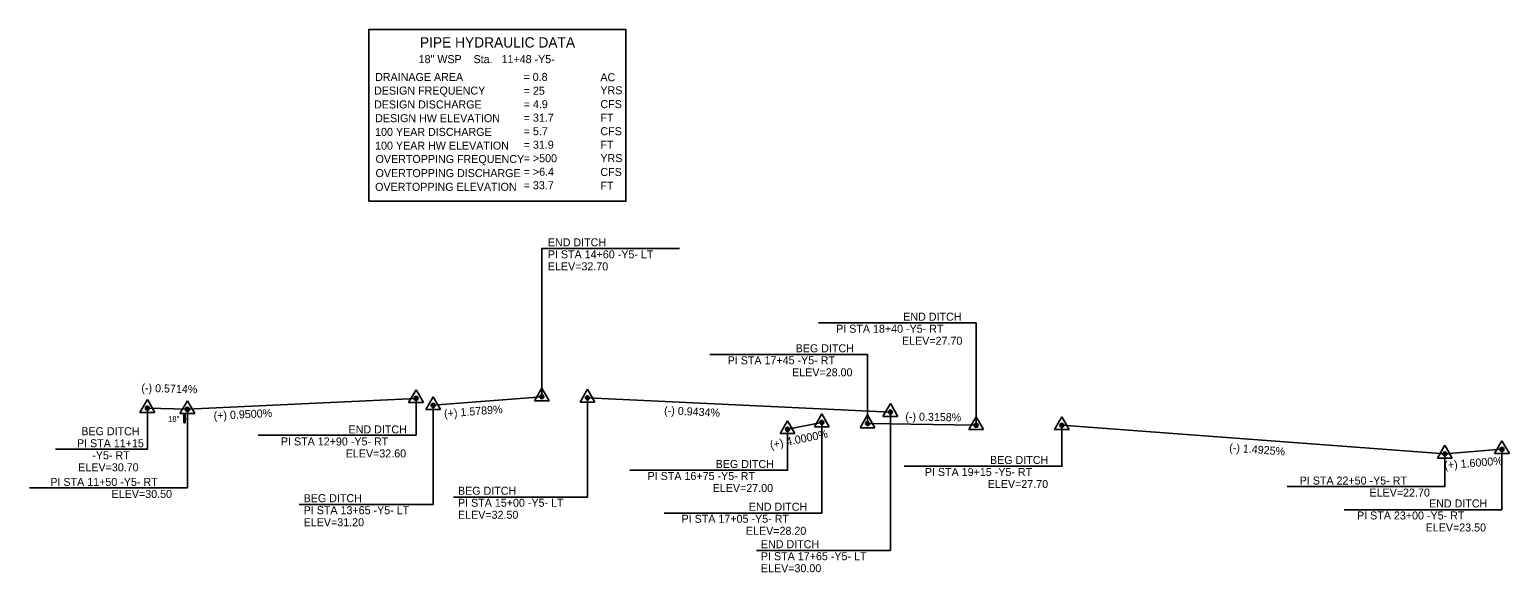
# Model space of a CAD drawing. Extents: x 2179808 to 2190174, y 63168 to 78602.
# Drawn here: x 2186620 to 2187914, y 72167 to 72642 of the extents above; entities that cross this region are included whole.
import ezdxf

# ---------------------------------------------------------------- set-up
doc = ezdxf.new("R2010")
doc.units = 0
for name, color, linetype in [('Default', 7, 'Continuous'), ('Prop Grid Mask', 7, 'Continuous'), ('Prop PFL Cross Pipe CELL', 7, 'Continuous'), ('Prop PFL Cross Pipe Text CELL', 7, 'Continuous'), ('Prop PFL Pipe Hydraulic Data CELL', 7, 'Continuous'), ('Prop Vertical Profile Ditch Grade Left', 7, 'Continuous'), ('Prop Vertical Profile Ditch Grade Left Label', 7, 'Continuous'), ('Prop Vertical Profile Ditch Grade Right', 7, 'Continuous'), ('Prop Vertical Profile Ditch Grade Right Label', 7, 'Continuous'), ('Prop VPI Ditch Grade Left Label', 7, 'Continuous'), ('Prop VPI Ditch Grade Right Label', 7, 'Continuous')]:
    doc.layers.add(name, color=color, linetype=linetype)

msp = doc.modelspace()

# ---------------------------------------------------------------- linework, layer by layer
at = {"layer": 'Default'}
for p, q in [((2186957.7, 72326.8), (2186951.2, 72315.6)), ((2186957.7, 72326.8), (2186964.2, 72315.6)), ((2187067.7, 72328.3), (2187061.2, 72317.1)), ((2187067.7, 72328.3), (2187074.2, 72317.1)), ((2187107.7, 72327.3), (2187101.2, 72316.1)), ((2187107.7, 72327.3), (2187114.2, 72316.1)), ((2186722.7, 72318.3), (2186716.2, 72307.1)), ((2186722.7, 72318.3), (2186729.2, 72307.1)), ((2186757.7, 72317.3), (2186751.2, 72306.1)), ((2186757.7, 72317.3), (2186764.2, 72306.1)), ((2186951.2, 72315.6), (2186964.2, 72315.6)), ((2186972.7, 72320.8), (2186966.2, 72309.6)), ((2186972.7, 72320.8), (2186979.2, 72309.6)), ((2187061.2, 72317.1), (2187074.2, 72317.1)), ((2187101.2, 72316.1), (2187114.2, 72316.1)), ((2187372.7, 72314.8), (2187366.2, 72303.6)), ((2187372.7, 72314.8), (2187379.2, 72303.6)), ((2186716.2, 72307.1), (2186729.2, 72307.1)), ((2186751.2, 72306.1), (2186764.2, 72306.1)), ((2186966.2, 72309.6), (2186979.2, 72309.6)), ((2187282.7, 72299.8), (2187276.2, 72288.6)), ((2187282.7, 72299.8), (2187289.2, 72288.6)), ((2187312.7, 72305.8), (2187306.2, 72294.6)), ((2187312.7, 72305.8), (2187319.2, 72294.6)), ((2187352.7, 72304.8), (2187346.2, 72293.6)), ((2187352.7, 72304.8), (2187359.2, 72293.6)), ((2187366.2, 72303.6), (2187379.2, 72303.6)), ((2187447.7, 72303.3), (2187441.2, 72292.1)), ((2187447.7, 72303.3), (2187454.2, 72292.1)), ((2187522.7, 72303.3), (2187516.2, 72292.1)), ((2187522.7, 72303.3), (2187529.2, 72292.1)), ((2187276.2, 72288.6), (2187289.2, 72288.6)), ((2187306.2, 72294.6), (2187319.2, 72294.6)), ((2187346.2, 72293.6), (2187359.2, 72293.6)), ((2187441.2, 72292.1), (2187454.2, 72292.1)), ((2187516.2, 72292.1), (2187529.2, 72292.1)), ((2187857.7, 72278.3), (2187851.2, 72267.1)), ((2187857.7, 72278.3), (2187864.2, 72267.1)), ((2187907.7, 72282.3), (2187901.2, 72271.1)), ((2187907.7, 72282.3), (2187914.2, 72271.1)), ((2187851.2, 72267.1), (2187864.2, 72267.1)), ((2187901.2, 72271.1), (2187914.2, 72271.1))]:
    msp.add_line(p, q, dxfattribs=at)
for centre, radius in [((2186722.7, 72310.8), 1.75), ((2186957.7, 72319.3), 1.75), ((2186957.7, 72319.3), 1.2), ((2186972.7, 72313.3), 1.75), ((2186972.7, 72313.3), 1.2), ((2187067.7, 72320.8), 1.75), ((2187067.7, 72320.8), 1.2), ((2187107.7, 72319.8), 1.75), ((2187107.7, 72319.8), 1.2), ((2186722.7, 72310.8), 1.2), ((2186757.7, 72309.8), 1.75), ((2186757.7, 72309.8), 1.2), ((2187312.7, 72298.3), 1.75), ((2187312.7, 72298.3), 1.2), ((2187372.7, 72307.3), 1.75), ((2187372.7, 72307.3), 1.2), ((2187282.7, 72292.3), 1.75), ((2187282.7, 72292.3), 1.2), ((2187352.7, 72297.3), 1.75), ((2187352.7, 72297.3), 1.2), ((2187447.7, 72295.8), 1.75), ((2187447.7, 72295.8), 1.2), ((2187522.7, 72295.8), 1.75), ((2187522.7, 72295.8), 1.2), ((2187907.7, 72274.8), 1.75), ((2187907.7, 72274.8), 1.2), ((2187857.7, 72270.8), 1.75), ((2187857.7, 72270.8), 1.2)]:
    msp.add_circle(centre, radius, dxfattribs=at)
at = {"layer": 'Prop Grid Mask'}
msp.add_lwpolyline([(2186916.3, 72491.6), (2187141.3, 72491.6), (2187141.3, 72641.6), (2186916.3, 72641.6)], close=True, dxfattribs=at)
at = {"layer": 'Prop PFL Cross Pipe CELL'}
msp.add_ellipse((2186755.2, 72301.5), major_axis=(0, 3.75), ratio=0.2, dxfattribs=at)
at = {"layer": 'Prop Vertical Profile Ditch Grade Left'}
for p, q in [((2186972.7, 72313.3), (2187067.7, 72320.8)), ((2187107.7, 72319.8), (2187372.7, 72307.3))]:
    msp.add_line(p, q, dxfattribs=at)
at = {"layer": 'Prop Vertical Profile Ditch Grade Right'}
for p, q in [((2187282.7, 72292.3), (2187312.7, 72298.3)), ((2187352.7, 72297.3), (2187447.7, 72295.8))]:
    msp.add_line(p, q, dxfattribs=at)
for points in [[(2186722.7, 72310.8), (2186757.7, 72309.8), (2186957.7, 72319.3)], [(2187522.7, 72295.8), (2187857.7, 72270.8), (2187907.7, 72274.8)]]:
    msp.add_lwpolyline(points, dxfattribs=at)
at = {"layer": 'Prop VPI Ditch Grade Left Label'}
for points in [[(2187067.7, 72320.8), (2187067.7, 72450.2), (2187188.3, 72450.2)], [(2186972.7, 72313.3), (2186972.7, 72226.6), (2186855.5, 72226.6)], [(2187107.7, 72319.8), (2187107.7, 72233.1), (2186990.5, 72233.1)], [(2187372.7, 72307.3), (2187372.7, 72186.4), (2187255.5, 72186.4)]]:
    msp.add_lwpolyline(points, dxfattribs=at)
for centre in [(2186972.7, 72313.3), (2187067.7, 72320.8), (2187107.7, 72319.8), (2187372.7, 72307.3)]:
    msp.add_circle(centre, 0.5, dxfattribs=at)
at = {"layer": 'Prop VPI Ditch Grade Right Label'}
for points in [[(2187447.7, 72295.8), (2187447.7, 72385.2), (2187309.7, 72385.2)], [(2187352.7, 72297.3), (2187352.7, 72357.6), (2187214.7, 72357.6)], [(2186957.7, 72319.3), (2186957.7, 72287.2), (2186819.7, 72287.2)], [(2186757.7, 72309.8), (2186757.7, 72241.2), (2186619.7, 72241.2)], [(2186722.7, 72310.8), (2186722.7, 72275), (2186642.2, 72275)], [(2187282.7, 72292.3), (2187282.7, 72256.5), (2187144.7, 72256.5)], [(2187312.7, 72298.3), (2187312.7, 72219.1), (2187174.7, 72219.1)], [(2187522.7, 72295.8), (2187522.7, 72260), (2187384.7, 72260)], [(2187907.7, 72274.8), (2187907.7, 72222), (2187769.7, 72222)], [(2187857.7, 72270.8), (2187857.7, 72242.4), (2187719.7, 72242.4)]]:
    msp.add_lwpolyline(points, dxfattribs=at)
for centre in [(2186957.7, 72319.3), (2186722.7, 72310.8), (2186757.7, 72309.8), (2187282.7, 72292.3), (2187312.7, 72298.3), (2187352.7, 72297.3), (2187447.7, 72295.8), (2187522.7, 72295.8), (2187907.7, 72274.8), (2187857.7, 72270.8)]:
    msp.add_circle(centre, 0.5, dxfattribs=at)

# ---------------------------------------------------------------- texts
at = {"layer": 'Prop PFL Cross Pipe Text CELL'}
msp.add_text('18"', height=5, dxfattribs=at).set_placement((2186740.8, 72298.8))
at = {"layer": 'Prop PFL Pipe Hydraulic Data CELL'}
for s, height, p in [('PIPE HYDRAULIC DATA', 9, (2186961.1, 72625.9)), ('  18" WSP    Sta.   11+48 -Y5-', 7, (2186954.8, 72612.3)), ('DRAINAGE AREA', 7, (2186921.9, 72596.7)), ('= 0.8    ', 7, (2187051.7, 72596.8)), ('AC', 7, (2187119, 72596.5)), ('DESIGN FREQUENCY', 7, (2186921, 72584.8)), ('= 25 ', 7, (2187051.9, 72584.7)), ('YRS', 7, (2187119, 72585.1)), ('DESIGN DISCHARGE', 7, (2186921, 72572.7)), ('= 4.9     ', 7, (2187051.9, 72572.9)), ('CFS', 7, (2187119, 72573)), ('DESIGN HW ELEVATION', 7, (2186921.9, 72560.7)), ('= 31.7    ', 7, (2187051.9, 72561.1)), ('FT', 7, (2187119, 72561.1)), ('100 YEAR DISCHARGE', 7, (2186921.9, 72548.7)), ('= 5.7     ', 7, (2187051.9, 72549.3)), ('CFS', 7, (2187119, 72549.3)), ('100 YEAR HW ELEVATION', 7, (2186921.9, 72536.7)), ('= 31.9    ', 7, (2187051.9, 72537.5)), ('= >500', 7, (2187051.9, 72525.7)), ('YRS', 7, (2187119, 72525.8)), ('FT', 7, (2187119, 72537.5)), ('OVERTOPPING FREQUENCY', 7, (2186922.3, 72525)), ('OVERTOPPING DISCHARGE', 7, (2186922.3, 72512.7)), ('= >6.4    ', 7, (2187051.9, 72513.9)), ('CFS', 7, (2187119, 72513.7)), ('OVERTOPPING ELEVATION', 7, (2186921.9, 72500.7)), ('= 33.7    ', 7, (2187051.9, 72502.1)), ('FT', 7, (2187119, 72501.7))]:
    msp.add_text(s, height=height, dxfattribs=at).set_placement(p)
at = {"layer": 'Prop Vertical Profile Ditch Grade Left Label'}
for s, rotation, p in [('(+) 1.5789%', 4.4926, (2186982.5, 72302.5)), ('(-) 0.9434%', 357.2994, (2187174.6, 72305.5))]:
    msp.add_text(s, height=7, rotation=rotation, dxfattribs=at).set_placement(p)
at = {"layer": 'Prop Vertical Profile Ditch Grade Right Label'}
for s, rotation, p in [('(-) 0.5714%', 358.3634, (2186717.4, 72325.1)), ('(+) 0.9500%', 2.7195, (2186780.8, 72300.7)), ('(-) 0.3158%', 359.0954, (2187385.7, 72300)), ('(+) 4.0000%', 11.3099, (2187268.1, 72275.1)), ('(-) 1.4925%', 355.7321, (2187668.9, 72273)), ('(+) 1.6000%', 4.5739, (2187857.5, 72257.4))]:
    msp.add_text(s, height=7, rotation=rotation, dxfattribs=at).set_placement(p)
at = {"layer": 'Prop VPI Ditch Grade Left Label'}
for s, p in [('END DITCH', (2187073, 72452.2)), ('PI STA 14+60 -Y5- LT', (2187073, 72441.7)), ('ELEV=32.70', (2187073, 72431.2)), ('BEG DITCH', (2186859.4, 72228.6)), ('BEG DITCH', (2186994.4, 72235.1)), ('PI STA 13+65 -Y5- LT', (2186859.4, 72218.1)), ('PI STA 15+00 -Y5- LT', (2186994.4, 72224.6)), ('ELEV=31.20', (2186859.4, 72207.6)), ('ELEV=32.50', (2186994.4, 72214.1)), ('END DITCH', (2187259.4, 72188.4)), ('PI STA 17+65 -Y5- LT', (2187259.4, 72177.9)), ('ELEV=30.00', (2187259.4, 72167.4))]:
    msp.add_text(s, height=7, dxfattribs=at).set_placement(p)
at = {"layer": 'Prop VPI Ditch Grade Right Label'}
for s, p in [('END DITCH', (2187383.9, 72387.2)), ('PI STA 18+40 -Y5- RT', (2187325.2, 72376.7)), ('ELEV=27.70', (2187382.8, 72366.2)), ('BEG DITCH', (2187459.8, 72262)), ('PI STA 19+15 -Y5- RT', (2187402.8, 72251.5)), ('ELEV=27.70', (2187457.8, 72241)), ('PI STA 22+50 -Y5- RT', (2187730.7, 72244)), ('ELEV=22.70', (2187791.8, 72233.5)), ('END DITCH', (2187248.9, 72221.1)), ('PI STA 17+05 -Y5- RT', (2187190, 72210.6)), ('ELEV=28.20', (2187246.3, 72200.1))]:
    msp.add_text(s, height=7, dxfattribs=at).set_placement(p)
for s, p in [('BEG DITCH', (2187289.8, 72359.6)), ('PI STA 17+45 -Y5- RT', (2187230.3, 72349.1)), ('ELEV=28.00', (2187286.7, 72338.6)), ('BEG DITCH', (2186664.9, 72287.1)), ('END DITCH', (2186898.7, 72288.7)), ('PI STA 11+15', (2186661.1, 72276.6)), ('PI STA 12+90 -Y5- RT', (2186839.5, 72278.2)), ('ELEV=32.60', (2186896.2, 72267.7)), ('ELEV=30.70', (2186662.2, 72255.6)), ('-Y5- RT', (2186674.5, 72266.1)), ('BEG DITCH', (2187219.8, 72258.5)), ('PI STA 11+50 -Y5- RT', (2186637.8, 72242.8)), ('PI STA 16+75 -Y5- RT', (2187160.3, 72248)), ('ELEV=30.50', (2186691.4, 72232.3)), ('ELEV=27.00', (2187217.2, 72237.5)), ('END DITCH', (2187843.9, 72224)), ('PI STA 23+00 -Y5- RT', (2187780.9, 72213.5)), ('ELEV=23.50', (2187840.9, 72203))]:
    msp.add_text(s, height=7, rotation=360, dxfattribs=at).set_placement(p)

doc.saveas('drawing.dxf')
